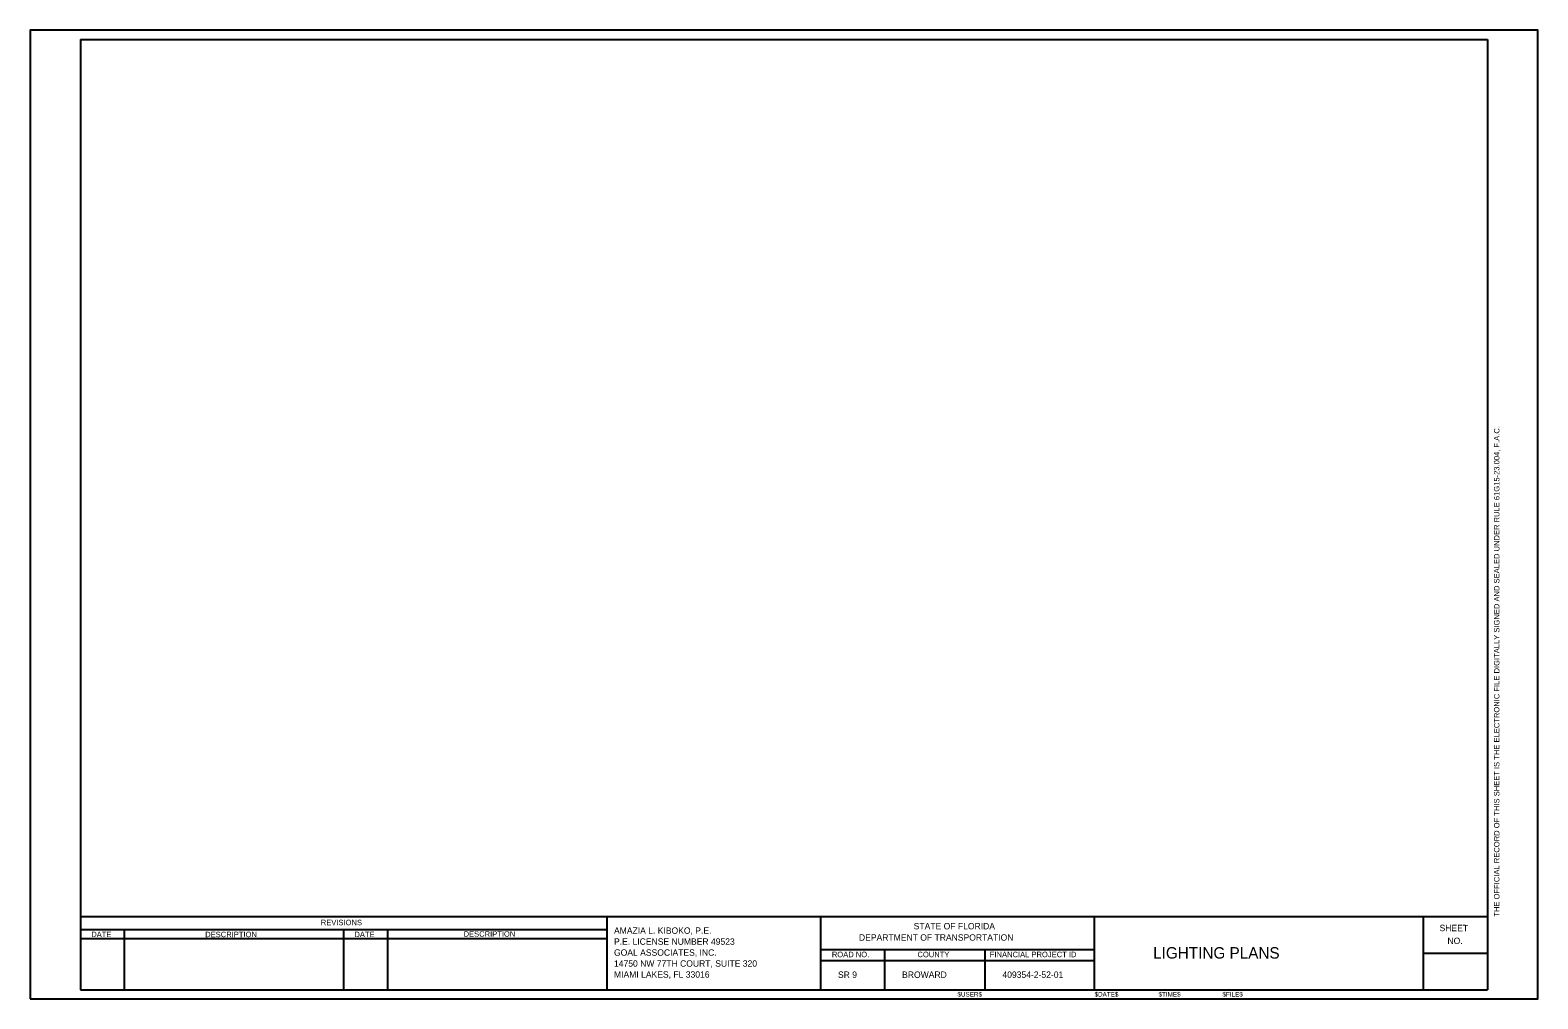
# Model space of a CAD drawing. Extents: x -816.7 to -800.2, y -2197.9 to -2187.3.
import ezdxf

# ---------------------------------------------------------------- set-up
doc = ezdxf.new("R2010")
doc.units = 0
for name, color, linetype in [('AdhocPoint_dp', 7, 'Continuous'), ('PlotBorder_dp', 7, 'Continuous'), ('SheetBorder_dp', 7, 'Continuous'), ('SheetLines_dp', 7, 'Continuous'), ('TextLabel', 7, 'Continuous'), ('TextMinor', 7, 'Continuous'), ('TextMisc', 7, 'Continuous'), ('TextTitle', 7, 'Continuous')]:
    doc.layers.add(name, color=color, linetype=linetype)

msp = doc.modelspace()

# ---------------------------------------------------------------- linework, layer by layer
at = {"layer": 'AdhocPoint_dp'}
msp.add_line((-816.669, -2197.899), (-816.669, -2197.899), dxfattribs=at)
msp.add_line((-816.669, -2197.899), (-816.669, -2197.899), dxfattribs=at)
at = {"layer": 'PlotBorder_dp'}
msp.add_lwpolyline([(-816.669, -2197.899), (-800.169, -2197.899), (-800.169, -2187.299), (-816.669, -2187.299)], close=True, dxfattribs=at)
at = {"layer": 'SheetBorder_dp'}
for p, q in [((-816.119, -2187.399), (-816.119, -2197.799)), ((-816.119, -2187.399), (-800.719, -2187.399)), ((-800.719, -2187.399), (-800.719, -2197.799)), ((-816.119, -2196.999), (-800.719, -2196.999)), ((-816.119, -2197.799), (-800.719, -2197.799))]:
    msp.add_line(p, q, dxfattribs=at)
at = {"layer": 'SheetLines_dp'}
for p, q in [((-816.119, -2197.139), (-810.359, -2197.139)), ((-815.639, -2197.139), (-815.639, -2197.799)), ((-813.239, -2197.139), (-813.239, -2197.799)), ((-812.759, -2197.139), (-812.759, -2197.799)), ((-810.359, -2196.999), (-810.359, -2197.799)), ((-808.019, -2196.999), (-808.019, -2197.799)), ((-805.019, -2197.799), (-805.019, -2196.999)), ((-801.419, -2197.799), (-801.419, -2196.999)), ((-816.119, -2197.239), (-810.359, -2197.239)), ((-808.019, -2197.359), (-805.019, -2197.359)), ((-807.319, -2197.359), (-807.319, -2197.799)), ((-806.219, -2197.359), (-806.219, -2197.799)), ((-801.419, -2197.399), (-800.719, -2197.399)), ((-808.019, -2197.479), (-805.019, -2197.479))]:
    msp.add_line(p, q, dxfattribs=at)

# ---------------------------------------------------------------- texts
at = {"layer": 'TextLabel'}
msp.add_text('        LIGHTING PLANS         ', height=0.125, dxfattribs=at).set_placement((-804.75, -2197.458))
at = {"layer": 'TextMinor'}
for s, height, rotation, p in [('THE OFFICIAL RECORD OF THIS SHEET IS THE ELECTRONIC FILE DIGITALLY SIGNED AND SEALED UNDER RULE 61G15-23.004, F.A.C.', 0.06, 90, (-800.589, -2196.999)), ('$DATE$', 0.05, 360, (-805.02, -2197.874)), ('$TIME$', 0.05, 360, (-804.32, -2197.874)), ('$FILE$', 0.05, 360, (-803.62, -2197.874))]:
    msp.add_text(s, height=height, rotation=rotation, dxfattribs=at).set_placement(p)
msp.add_text('$USER$', height=0.05, dxfattribs=at).set_placement((-806.52, -2197.874))
at = {"layer": 'TextMisc'}
for s, height, p in [('REVISIONS', 0.06, (-813.488, -2197.093)), ('STATE OF FLORIDA', 0.07, (-806.999, -2197.138)), ('DEPARTMENT OF TRANSPORTATION', 0.07, (-807.598, -2197.262)), ('ROAD NO.', 0.06, (-807.895, -2197.443)), ('COUNTY', 0.06, (-806.958, -2197.443)), ('FINANCIAL PROJECT ID', 0.06, (-806.166, -2197.443)), (' SR 9  ', 0.07, (-807.854, -2197.669)), ('  BROWARD   ', 0.07, (-807.178, -2197.669)), ('409354-2-52-01', 0.07, (-806.028, -2197.669))]:
    msp.add_text(s, height=height, dxfattribs=at).set_placement(p)
for s, height, rotation, p in [('SHEET', 0.07, 359.8607, (-801.244, -2197.158)), ('DATE', 0.06, 359.8693, (-816, -2197.223)), ('DESCRIPTION', 0.06, 0.0498, (-814.753, -2197.224)), ('DATE', 0.06, 359.8693, (-813.12, -2197.223)), ('DESCRIPTION', 0.06, 0.0498, (-811.925, -2197.219)), ('NO.', 0.07, 359.8607, (-801.158, -2197.298))]:
    msp.add_text(s, height=height, rotation=rotation, dxfattribs=at).set_placement(p)
at = {"layer": 'TextTitle'}
for s, p in [('AMAZIA L. KIBOKO, P.E.', (-810.279, -2197.187)), ('P.E. LICENSE NUMBER 49523', (-810.279, -2197.307)), ('GOAL ASSOCIATES, INC.', (-810.279, -2197.427)), ('14750 NW 77TH COURT, SUITE 320', (-810.279, -2197.547)), ('MIAMI LAKES, FL 33016', (-810.279, -2197.667))]:
    msp.add_text(s, height=0.07, dxfattribs=at).set_placement(p)

doc.saveas('drawing.dxf')
